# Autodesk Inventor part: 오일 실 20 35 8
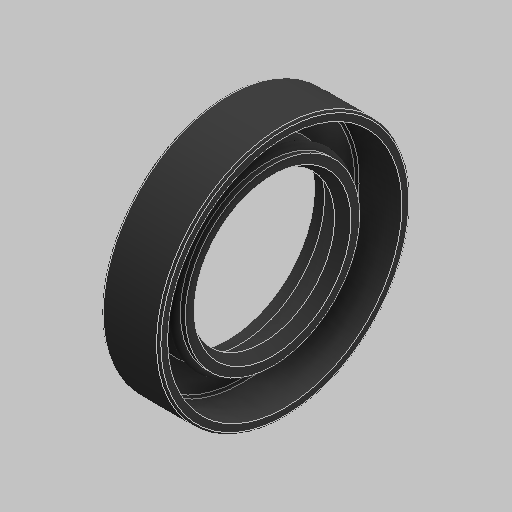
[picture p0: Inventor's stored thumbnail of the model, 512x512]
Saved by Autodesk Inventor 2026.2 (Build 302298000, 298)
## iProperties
Created: 2026-06
Part Number: 오일 실 20 35 8
Material: 고무
Description: 오일-실
Document SubType Name: Modeling
Designer: sec7
Density: 0.93 g/cm^3
Appearance: 기본값
Author: jhkim
Sending System: Autodesk Inventor 2027
Preprocessor: ST-DEVELOPER v20.1
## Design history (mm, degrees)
feature "Solid1"
node "솔리드1"
